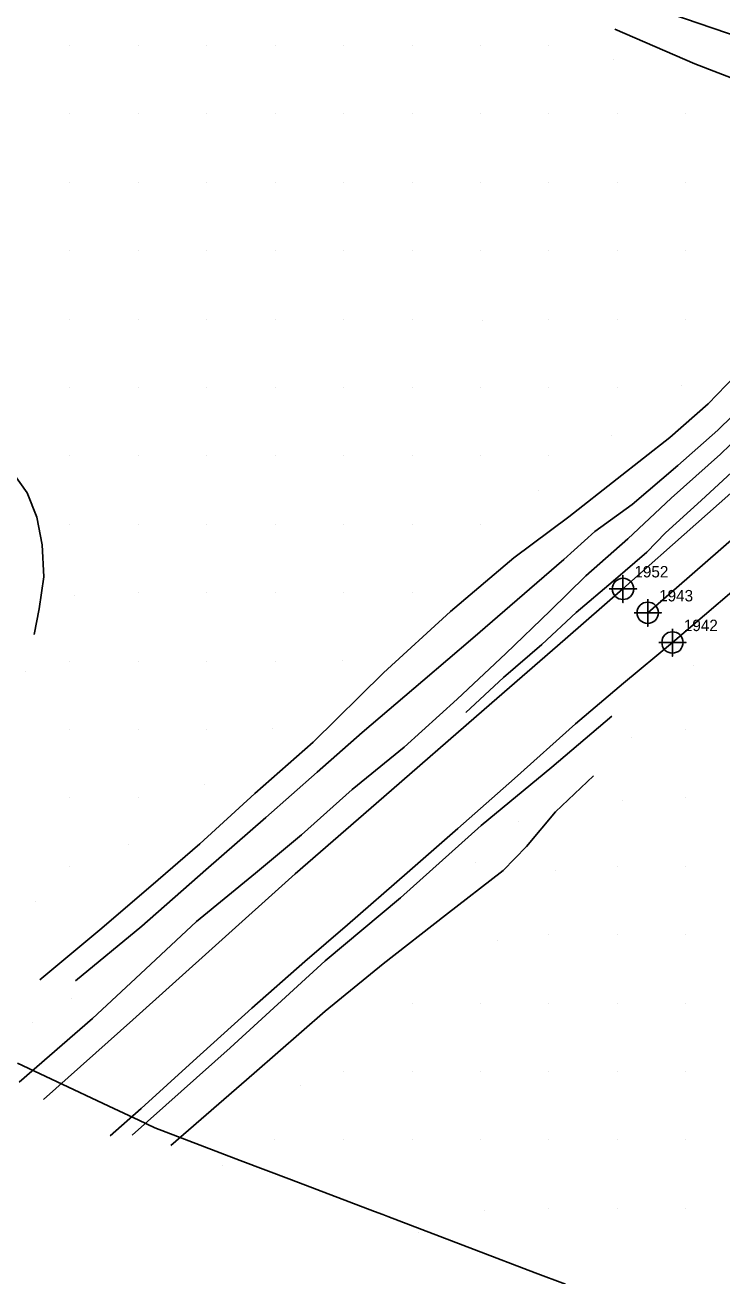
# Model space of a CAD drawing. Extents: x 1497074 to 1501343, y 481943 to 486114.
# Drawn here: x 1499690.7 to 1499843.4, y 482477.4 to 482751.7 of the extents above; entities that cross this region are included whole.
import ezdxf

# ---------------------------------------------------------------- set-up
doc = ezdxf.new("R2010")
doc.units = 0
for name, color, linetype in [('Exist DTM Crownline', 7, 'Continuous'), ('Exist DTM Crownline Cogo Number', 7, 'Continuous'), ('Exist DTM Crownline Cogo Point CELL', 7, 'Continuous'), ('Exist Roads EOP', 7, 'Continuous'), ('Exist Roads EOP Cogo Number', 7, 'Continuous'), ('Exist Roads EOP Cogo Point CELL', 7, 'Continuous'), ('PH Exist DTM Boundary', 7, 'Continuous'), ('PH Exist DTM Breakline', 7, 'Continuous'), ('PH Exist DTM Point', 7, 'Continuous')]:
    doc.layers.add(name, color=color, linetype=linetype)

msp = doc.modelspace()

# ---------------------------------------------------------------- linework, layer by layer
at = {"layer": 'Exist DTM Crownline'}
msp.add_lwpolyline([(1499827.14, 482622.78), (1499859.17, 482650.66), (1499881.64, 482670.46), (1499896.81, 482685.74), (1499916.4, 482710.08), (1499925.49, 482726.41), (1499926.19, 482727.72)], dxfattribs=at)
at = {"layer": 'Exist DTM Crownline Cogo Point CELL'}
msp.add_lwpolyline([(1499827.14, 482625.78), (1499827.14, 482619.78), (1499827.14, 482622.78), (1499830.14, 482622.78), (1499824.14, 482622.78)], dxfattribs=at)
msp.add_circle((1499827.14, 482622.78), 2.34, dxfattribs=at)
at = {"layer": 'Exist Roads EOP'}
for points in [[(1499821.72, 482628.03), (1499853.66, 482656.41), (1499874.77, 482677.9), (1499888.46, 482693.89), (1499887.41, 482695.08), (1499900.17, 482716.32), (1499901.17, 482722.82), (1499900.82, 482727.27), (1499897.51, 482732.26), (1499893.81, 482737), (1499890.76, 482740.13), (1499879.42, 482746.57), (1499858.29, 482754.73), (1499814.16, 482772.08), (1499767.71, 482791.06), (1499743.71, 482801.5), (1499721.28, 482811.45), (1499698.51, 482821.61), (1499675.14, 482832.32)], [(1500364.14, 482572.31), (1500324.1, 482586.71), (1500274.47, 482604.24), (1500226.4, 482621.51), (1500172.89, 482640.65), (1500123.05, 482658.39), (1500072.51, 482676.64), (1500021.62, 482694.94), (1499975.28, 482711.55), (1499955.26, 482716.33), (1499949.38, 482714.38), (1499941.38, 482710.37), (1499928.12, 482699.94), (1499921.66, 482694.39), (1499904.23, 482677.62), (1499903.33, 482678.08), (1499900.77, 482675.86), (1499864.51, 482643.53), (1499854.11, 482635.15), (1499853.12, 482633.84), (1499832.56, 482616.27)]]:
    msp.add_lwpolyline(points, dxfattribs=at)
at = {"layer": 'Exist Roads EOP Cogo Point CELL'}
for points in [[(1499821.72, 482631.03), (1499821.72, 482625.03), (1499821.72, 482628.03), (1499824.72, 482628.03), (1499818.72, 482628.03)], [(1499832.56, 482619.27), (1499832.56, 482613.27), (1499832.56, 482616.27), (1499835.56, 482616.27), (1499829.56, 482616.27)]]:
    msp.add_lwpolyline(points, dxfattribs=at)
for centre in [(1499821.72, 482628.03), (1499832.56, 482616.27)]:
    msp.add_circle(centre, 2.34, dxfattribs=at)
at = {"layer": 'PH Exist DTM Boundary'}
msp.add_lwpolyline([(1499689.09, 482524.05), (1499697.62, 482520.02), (1499709.09, 482514.6), (1499715.66, 482511.49), (1499719.18, 482509.83), (1499719.18, 482509.83), (1499729.09, 482506.05), (1499737.88, 482502.7), (1499749.09, 482498.43), (1499767.31, 482491.49), (1499769.09, 482490.81), (1499770.19, 482490.39), (1499789.09, 482483.19), (1499802.5, 482478.08), (1499809.09, 482475.57)], dxfattribs=at)
at = {"layer": 'PH Exist DTM Breakline'}
for points in [[(1499699.65, 482810.33), (1499725.57, 482798.37), (1499747.32, 482788.27), (1499771.85, 482778.33), (1499801.92, 482765.83), (1499832, 482754.22), (1499854, 482746.66), (1499870.21, 482741.39), (1499878.83, 482738.17)], [(1499848.66, 482738.84), (1499837.47, 482743.12), (1499819.91, 482750.73)], [(1499694, 482542.28), (1499707.09, 482553.26), (1499718.28, 482562.84), (1499729.05, 482572.11), (1499741.06, 482583.15), (1499753.83, 482594.39), (1499769.22, 482609.62), (1499783.92, 482623.09), (1499797.84, 482634.8), (1499809.82, 482643.85), (1499820.41, 482652.12), (1499831.96, 482661.25), (1499840.37, 482668.57), (1499848.3, 482676.77)], [(1499663.29, 482670.45), (1499674.48, 482663.8), (1499682.04, 482659.09), (1499687.61, 482654.1), (1499691.23, 482649.08), (1499693.34, 482643.75), (1499694.5, 482637.7), (1499694.84, 482630.63), (1499693.8, 482623.64), (1499692.76, 482618)], [(1499701.76, 482542.1), (1499716.34, 482554.08), (1499730.32, 482566.41), (1499743.46, 482577.88), (1499754.75, 482587.87), (1499764.56, 482596.54), (1499777.85, 482607.83), (1499788.83, 482617.22), (1499798.52, 482625.65), (1499808.75, 482634.5), (1499815.56, 482640.58), (1499823.76, 482646.53), (1499833.72, 482655.06), (1499842.52, 482662.8), (1499848.98, 482669.22)], [(1499851.56, 482665.75), (1499843.06, 482657.55), (1499832.31, 482647.9), (1499822.8, 482639.02), (1499813.59, 482630.85), (1499805.79, 482623.24), (1499796.08, 482613.84), (1499785.4, 482603.86), (1499773.76, 482593.33), (1499762.37, 482584.04), (1499751.3, 482574.09), (1499741.19, 482565.69), (1499728.32, 482555.06), (1499716.04, 482543.6), (1499705.54, 482533.8), (1499689.45, 482519.83)], [(1499848.43, 482656.26), (1499838.84, 482647.39), (1499831.02, 482640.28), (1499826.95, 482636.04), (1499819.57, 482629.7), (1499811.46, 482622.82), (1499803.95, 482615.81), (1499795.52, 482608.6), (1499787.27, 482600.93)], [(1499694.76, 482516.05), (1499714.33, 482533.55), (1499732.46, 482549.85), (1499749.93, 482565.56), (1499769.32, 482582.46), (1499791.31, 482601.58), (1499809.08, 482617), (1499821.72, 482628.03)], [(1499832.56, 482616.27), (1499821.85, 482607.34), (1499811.32, 482598.46), (1499797.92, 482586.47), (1499785.54, 482575.46), (1499774.41, 482565.78), (1499761.4, 482554.37), (1499752.01, 482546.3), (1499740.42, 482536.05), (1499727.53, 482524.46), (1499716.19, 482514.1), (1499709.35, 482508.1)], [(1499714.23, 482508.23), (1499735.68, 482527.41), (1499756.5, 482546.49), (1499772.96, 482560.31), (1499790.62, 482576.12), (1499806.11, 482588.93), (1499819.24, 482600.1)], [(1499722.64, 482505.94), (1499740.89, 482521.84), (1499756.51, 482535.42), (1499769.17, 482545.79), (1499782.85, 482556.45), (1499795.5, 482566.26), (1499800.6, 482571.57), (1499806.97, 482579.1), (1499815.26, 482587)]]:
    msp.add_lwpolyline(points, dxfattribs=at)
at = {"layer": 'PH Exist DTM Point'}
for p, q in [((1499700.5, 482747.19), (1499700.5, 482747.19)), ((1499715.5, 482747.19), (1499715.5, 482747.19)), ((1499730.5, 482747.19), (1499730.5, 482747.19)), ((1499745.5, 482747.19), (1499745.5, 482747.19)), ((1499760.5, 482747.19), (1499760.5, 482747.19)), ((1499775.5, 482747.19), (1499775.5, 482747.19)), ((1499790.5, 482747.19), (1499790.5, 482747.19)), ((1499805.5, 482747.19), (1499805.5, 482747.19)), ((1499819.66, 482744.11), (1499819.66, 482744.11)), ((1499700.5, 482732.19), (1499700.5, 482732.19)), ((1499715.5, 482732.19), (1499715.5, 482732.19)), ((1499730.5, 482732.19), (1499730.5, 482732.19)), ((1499745.5, 482732.19), (1499745.5, 482732.19)), ((1499760.5, 482732.19), (1499760.5, 482732.19)), ((1499775.5, 482732.19), (1499775.5, 482732.19)), ((1499790.5, 482732.19), (1499790.5, 482732.19)), ((1499805.5, 482732.19), (1499805.5, 482732.19)), ((1499820.5, 482732.19), (1499820.5, 482732.19)), ((1499835.5, 482732.19), (1499835.5, 482732.19)), ((1499700.5, 482717.19), (1499700.5, 482717.19)), ((1499715.5, 482717.19), (1499715.5, 482717.19)), ((1499730.5, 482717.19), (1499730.5, 482717.19)), ((1499745.5, 482717.19), (1499745.5, 482717.19)), ((1499760.5, 482717.19), (1499760.5, 482717.19)), ((1499775.5, 482717.19), (1499775.5, 482717.19)), ((1499790.5, 482717.19), (1499790.5, 482717.19)), ((1499805.5, 482717.19), (1499805.5, 482717.19)), ((1499820.5, 482717.19), (1499820.5, 482717.19)), ((1499835.5, 482717.19), (1499835.5, 482717.19)), ((1499700.5, 482702.19), (1499700.5, 482702.19)), ((1499715.5, 482702.19), (1499715.5, 482702.19)), ((1499730.5, 482702.19), (1499730.5, 482702.19)), ((1499745.5, 482702.19), (1499745.5, 482702.19)), ((1499760.5, 482702.19), (1499760.5, 482702.19)), ((1499775.5, 482702.19), (1499775.5, 482702.19)), ((1499790.5, 482702.19), (1499790.5, 482702.19)), ((1499805.5, 482702.19), (1499805.5, 482702.19)), ((1499820.5, 482702.19), (1499820.5, 482702.19)), ((1499835.5, 482702.19), (1499835.5, 482702.19)), ((1499700.5, 482687.19), (1499700.5, 482687.19)), ((1499715.5, 482687.19), (1499715.5, 482687.19)), ((1499730.5, 482687.19), (1499730.5, 482687.19)), ((1499745.5, 482687.19), (1499745.5, 482687.19)), ((1499760.5, 482687.19), (1499760.5, 482687.19)), ((1499775.5, 482687.19), (1499775.5, 482687.19)), ((1499790.88, 482686.98), (1499790.88, 482686.98)), ((1499805.5, 482687.19), (1499805.5, 482687.19)), ((1499820.5, 482687.19), (1499820.5, 482687.19)), ((1499835.5, 482687.19), (1499835.5, 482687.19)), ((1499700.5, 482672.19), (1499700.5, 482672.19)), ((1499715.5, 482672.19), (1499715.5, 482672.19)), ((1499730.5, 482672.19), (1499730.5, 482672.19)), ((1499745.5, 482672.19), (1499745.5, 482672.19)), ((1499760.5, 482672.19), (1499760.5, 482672.19)), ((1499775.5, 482672.19), (1499775.5, 482672.19)), ((1499790.5, 482672.19), (1499790.5, 482672.19)), ((1499805.5, 482672.19), (1499805.5, 482672.19)), ((1499820.5, 482672.19), (1499820.5, 482672.19)), ((1499834.56, 482672.71), (1499834.56, 482672.71)), ((1499819.3, 482661.58), (1499819.3, 482661.58)), ((1499700.5, 482657.19), (1499700.5, 482657.19)), ((1499715.5, 482657.19), (1499715.5, 482657.19)), ((1499730.5, 482657.19), (1499730.5, 482657.19)), ((1499745.5, 482657.19), (1499745.5, 482657.19)), ((1499760.5, 482657.19), (1499760.5, 482657.19)), ((1499775.5, 482657.19), (1499775.5, 482657.19)), ((1499790.5, 482657.19), (1499790.5, 482657.19)), ((1499805.5, 482657.19), (1499805.5, 482657.19)), ((1499803.29, 482649.53), (1499803.29, 482649.53)), ((1499700.5, 482642.19), (1499700.5, 482642.19)), ((1499715.5, 482642.19), (1499715.5, 482642.19)), ((1499730.5, 482642.19), (1499730.5, 482642.19)), ((1499745.5, 482642.19), (1499745.5, 482642.19)), ((1499760.5, 482642.19), (1499760.5, 482642.19)), ((1499775.5, 482642.19), (1499775.5, 482642.19)), ((1499790.5, 482642.19), (1499790.5, 482642.19)), ((1499701.56, 482626.61), (1499701.56, 482626.61)), ((1499715.5, 482627.19), (1499715.5, 482627.19)), ((1499730.5, 482627.19), (1499730.5, 482627.19)), ((1499745.5, 482627.19), (1499745.5, 482627.19)), ((1499760.5, 482627.19), (1499760.5, 482627.19)), ((1499775.51, 482627.22), (1499775.51, 482627.22)), ((1499700.5, 482612.19), (1499700.5, 482612.19)), ((1499715.5, 482612.19), (1499715.5, 482612.19)), ((1499730.5, 482612.19), (1499730.5, 482612.19)), ((1499745.5, 482612.19), (1499745.5, 482612.19)), ((1499760.37, 482612.26), (1499760.37, 482612.26)), ((1499690.81, 482609.98), (1499690.81, 482609.98)), ((1499837.09, 482611.32), (1499837.09, 482611.32)), ((1499700.5, 482597.19), (1499700.5, 482597.19)), ((1499715.5, 482597.19), (1499715.5, 482597.19)), ((1499730.5, 482597.19), (1499730.5, 482597.19)), ((1499744.96, 482597.48), (1499744.96, 482597.48)), ((1499823.57, 482595.52), (1499823.57, 482595.52)), ((1499835.5, 482597.19), (1499835.5, 482597.19)), ((1499730.07, 482585.06), (1499730.07, 482585.06)), ((1499700.5, 482582.19), (1499700.5, 482582.19)), ((1499715.5, 482582.19), (1499715.5, 482582.19)), ((1499821.64, 482581.57), (1499821.64, 482581.57)), ((1499835.5, 482582.19), (1499835.5, 482582.19)), ((1499798.74, 482577.07), (1499798.74, 482577.07)), ((1499713.42, 482571.98), (1499713.42, 482571.98)), ((1499789.51, 482567.96), (1499789.51, 482567.96)), ((1499700.5, 482567.19), (1499700.5, 482567.19)), ((1499806.98, 482566.38), (1499806.98, 482566.38)), ((1499820.5, 482567.19), (1499820.5, 482567.19)), ((1499835.5, 482567.19), (1499835.5, 482567.19)), ((1499692.99, 482559.47), (1499692.99, 482559.47)), ((1499805.5, 482552.19), (1499805.5, 482552.19)), ((1499820.5, 482552.19), (1499820.5, 482552.19)), ((1499835.5, 482552.19), (1499835.5, 482552.19)), ((1499794.26, 482550.82), (1499794.26, 482550.82)), ((1499700.94, 482538.11), (1499700.94, 482538.11)), ((1499775.5, 482537.19), (1499775.5, 482537.19)), ((1499790.5, 482537.19), (1499790.5, 482537.19)), ((1499805.5, 482537.19), (1499805.5, 482537.19)), ((1499820.5, 482537.19), (1499820.5, 482537.19)), ((1499835.5, 482537.19), (1499835.5, 482537.19)), ((1499692.4, 482532.97), (1499692.4, 482532.97)), ((1499760.5, 482522.19), (1499760.5, 482522.19)), ((1499775.58, 482522.14), (1499775.58, 482522.14)), ((1499790.5, 482522.19), (1499790.5, 482522.19)), ((1499805.5, 482522.19), (1499805.5, 482522.19)), ((1499820.5, 482522.19), (1499820.5, 482522.19)), ((1499835.5, 482522.19), (1499835.5, 482522.19)), ((1499751.04, 482519.17), (1499751.04, 482519.17)), ((1499745.45, 482507.22), (1499745.45, 482507.22)), ((1499760.5, 482507.19), (1499760.5, 482507.19)), ((1499775.5, 482507.19), (1499775.5, 482507.19)), ((1499790.5, 482507.19), (1499790.5, 482507.19)), ((1499805.5, 482507.19), (1499805.5, 482507.19)), ((1499820.5, 482507.19), (1499820.5, 482507.19)), ((1499835.5, 482507.19), (1499835.5, 482507.19)), ((1499734.03, 482501.55), (1499734.03, 482501.55)), ((1499791.29, 482491.77), (1499791.29, 482491.77)), ((1499805.5, 482492.19), (1499805.5, 482492.19)), ((1499820.5, 482492.19), (1499820.5, 482492.19)), ((1499835.5, 482492.19), (1499835.5, 482492.19)), ((1499776.88, 482486.84), (1499776.88, 482486.84))]:
    msp.add_line(p, q, dxfattribs=at)

# ---------------------------------------------------------------- texts
at = {"layer": 'Exist DTM Crownline Cogo Number'}
msp.add_text('1943', height=2.5, dxfattribs=at).set_placement((1499829.64, 482625.28))
at = {"layer": 'Exist Roads EOP Cogo Number'}
for s, p in [('1952', (1499824.22, 482630.54)), ('1942', (1499835.06, 482618.77))]:
    msp.add_text(s, height=2.5, dxfattribs=at).set_placement(p)

doc.saveas('drawing.dxf')
